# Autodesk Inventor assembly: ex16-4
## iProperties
Shininess: 64.0
Length Units: 11269
Angle Units: 11279
Time Units: 11290
Mass Units: 11283
Length Display Precision: 3
Angle Display Precision: 2
Compacted: True
Created: 2002-11
Part Number: ex16-4
Document SubType Name: Assembly
Designer: E. MOSS
Density: 0.0
Volumn: 0.0
Area: 0.0
PropertySet Name: Model Information
Control State: 0
Master: False
Checked Out: False
Author: E. MOSS
